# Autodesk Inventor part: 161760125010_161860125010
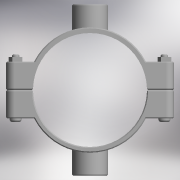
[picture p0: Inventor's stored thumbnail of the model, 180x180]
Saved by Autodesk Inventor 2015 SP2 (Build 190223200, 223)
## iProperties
Created: 2017-05
Part Number: 161760125010_161860125010
Material: Generic
Description: PLASSON DOUBLE SADDLE 125-1"
Document SubType Name: Modeling
Designer: KIM
Density: 1 g/cm^3
Appearance: Default
Author: KIM
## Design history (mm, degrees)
derived "16176.ipt"
feature "Solid1::16176.ipt"
feature "Solid2::16176.ipt"
tag "TaggingFeature1"
body "Solid1"
body "Solid2"
other parameters: "d0" = 137.5, "d1" = 184, "d2" = 62.5, "d3" = 125, "d4" = 124, "d5" = 0, "d6" = 9.2, "d7" = 184, "d8" = 0.1, "d10" = 0, "d11" = 1.25, "d20" = 1.25, "d23" = 1.25, "d36" = 13, "d37" = 10.4, "d38" = 70.5, "d39" = 0, "d40" = 3, "d41" = 5, "d42" = 0, "d43" = 8, "d44" = 3, "d45" = 0, "d46" = 1.25, "d52" = 30.291, "d53" = 21, "d54" = 0, "d55" = 25, "d57" = 0, "d58" = 135, "d60" = 0, "d62" = 13, "d63" = 10.4, "d66" = 103.2, "d67" = 188, "d68" = 39.3783, "d69" = 30.291, "d70" = 21, "d71" = 0, "d72" = 25, "d74" = 0, "d75" = 1.25, "d_" = 125, "B_" = 25, "G_" = 30.291, "A_" = 94, "L_" = 184, "L_1" = 124, "l_2" = 21
